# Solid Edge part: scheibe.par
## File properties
Title: Beilagscheibe
Subject: Schmiege
Author: rauh
Template: Normal.par
Last saved by: ra-tv
Revision: 2
Application: Solid Edge
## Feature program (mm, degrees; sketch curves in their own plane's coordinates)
sketch for "unnamed Protrusion 1" plane through (0, 0, 0) normal (0, 0, 1) x-axis (1, 0, 0)
  circle centre (0, 0) radius 10
extrude "unnamed Protrusion 1" add finite 4 symmetric
sketch for "unnamed Cutout 1" plane through (0, 0, 2) normal (0, 0, 1) x-axis (0, 1, 0)
  circle centre (0, 0) radius 4.15
extrude "unnamed Cutout 1" cut finite 120.65 symmetric
